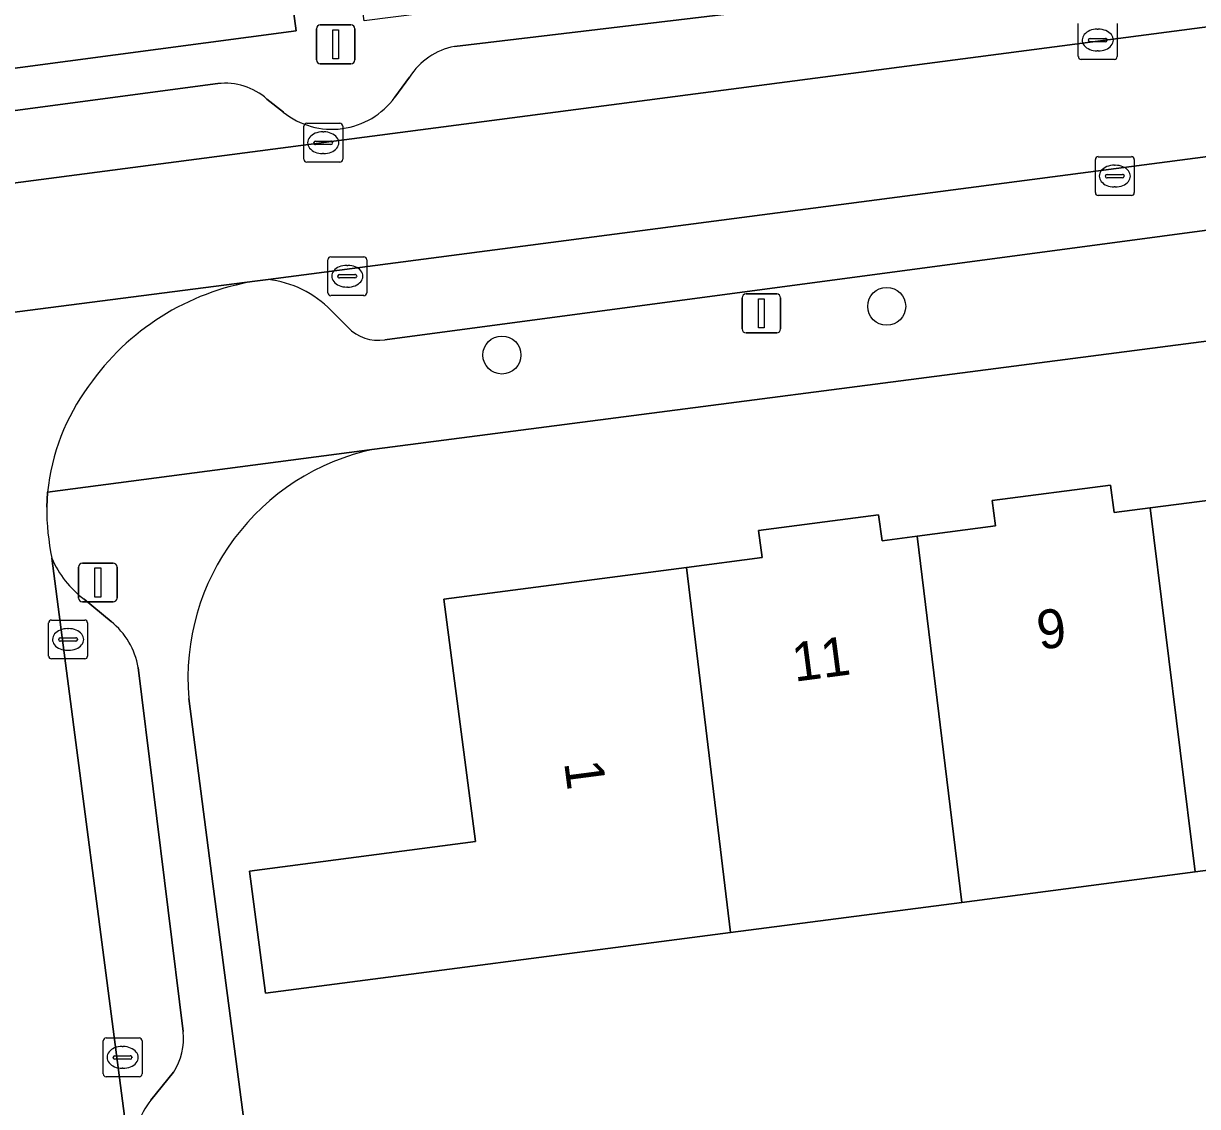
# Model space of a CAD drawing. Extents: x 162073 to 163043, y 381818 to 382561.
# Drawn here: x 162410.5 to 162440.71, y 382437.39 to 382465.27 of the extents above; entities that cross this region are included whole.
import ezdxf

# ---------------------------------------------------------------- set-up
doc = ezdxf.new("R2010")
doc.units = 0
for name, color, linetype in [('IMGEO_Boom', 7, 'Continuous'), ('IMGEO_Erf', 7, 'Continuous'), ('IMGEO_Groenvoorziening', 7, 'Continuous'), ('IMGEO_Kolk', 7, 'Continuous'), ('IMGEO_Lichtmast', 7, 'Continuous'), ('IMGEO_Muur', 7, 'Continuous'), ('IMGEO_Pand', 7, 'Continuous'), ('IMGEO_Pand_nummerreeks', 7, 'Continuous'), ('IMGEO_Parkeervlak_open', 7, 'Continuous'), ('IMGEO_Rijbaan_lokaal_open', 7, 'Continuous'), ('IMGEO_Voetpad_open', 7, 'Continuous')]:
    doc.layers.add(name, color=color, linetype=linetype)

msp = doc.modelspace()

# ---------------------------------------------------------------- linework, layer by layer
at = {"layer": 'IMGEO_Boom'}
for centre in [(162432.708, 382457.989), (162422.807, 382456.736)]:
    msp.add_circle(centre, 0.489, dxfattribs=at)
at = {"layer": 'IMGEO_Erf'}
for points in [[(162462.605, 382459.91), (162419.532, 382454.313)], [(162446.564, 382444.204), (162440.645, 382443.431), (162434.645, 382442.648), (162428.685, 382441.87), (162416.724, 382440.308), (162416.313, 382443.452), (162422.131, 382444.212), (162421.316, 382450.456), (162427.553, 382451.271), (162429.5, 382451.525), (162429.41, 382452.218), (162432.501, 382452.622), (162432.588, 382451.956), (162433.495, 382452.075), (162435.509, 382452.338), (162435.424, 382452.989), (162438.469, 382453.386), (162438.561, 382452.68), (162439.485, 382452.801), (162441.425, 382453.054)], [(162414.747, 382447.893), (162415.345, 382443.326), (162417.254, 382428.746)]]:
    msp.add_lwpolyline(points, dxfattribs=at)
msp.add_arc((162420.754, 382448.409), 6.029, 101.6965, 184.9072, dxfattribs=at)
at = {"layer": 'IMGEO_Groenvoorziening'}
msp.add_lwpolyline([(162416.769, 382470.6), (162396.812, 382467.987), (162397.548, 382462.43), (162417.516, 382465.082)], close=True, dxfattribs=at)
at = {"layer": 'IMGEO_Kolk'}
for p, q in [((162437.639, 382464.417), (162437.639, 382465.269)), ((162438.127, 382465.123), (162438.152, 382465.123)), ((162438.64, 382465.269), (162438.64, 382464.417)), ((162437.898, 382464.837), (162437.898, 382464.849)), ((162438.336, 382464.8), (162437.938, 382464.8)), ((162437.941, 382464.886), (162438.339, 382464.886)), ((162438.382, 382464.849), (162438.382, 382464.837)), ((162438.15, 382464.563), (162438.125, 382464.563)), ((162438.566, 382464.343), (162437.714, 382464.343)), ((162417.783, 382462.699), (162418.635, 382462.699)), ((162417.708, 382461.773), (162417.708, 382462.625)), ((162418.196, 382462.479), (162418.221, 382462.479)), ((162418.709, 382462.625), (162418.709, 382461.773)), ((162417.967, 382462.193), (162417.967, 382462.205)), ((162418.405, 382462.156), (162418.007, 382462.156)), ((162418.01, 382462.242), (162418.408, 382462.242)), ((162418.451, 382462.205), (162418.451, 382462.193)), ((162418.219, 382461.919), (162418.194, 382461.919)), ((162438.078, 382460.915), (162438.078, 382461.767)), ((162438.153, 382461.841), (162439.005, 382461.841)), ((162439.079, 382461.767), (162439.079, 382460.915)), ((162418.635, 382461.699), (162417.783, 382461.699)), ((162438.566, 382461.621), (162438.591, 382461.621)), ((162438.337, 382461.335), (162438.337, 382461.347)), ((162438.775, 382461.298), (162438.377, 382461.298)), ((162438.38, 382461.384), (162438.778, 382461.384)), ((162438.821, 382461.347), (162438.821, 382461.335)), ((162439.005, 382460.841), (162438.153, 382460.841)), ((162438.589, 382461.061), (162438.564, 382461.061)), ((162418.326, 382458.338), (162418.326, 382459.19)), ((162418.401, 382459.264), (162419.253, 382459.264)), ((162418.814, 382459.044), (162418.839, 382459.044)), ((162419.327, 382459.19), (162419.327, 382458.338)), ((162418.585, 382458.758), (162418.585, 382458.77)), ((162418.628, 382458.807), (162419.026, 382458.807)), ((162419.069, 382458.77), (162419.069, 382458.758)), ((162419.023, 382458.721), (162418.625, 382458.721)), ((162418.837, 382458.484), (162418.812, 382458.484)), ((162419.253, 382458.264), (162418.401, 382458.264)), ((162411.143, 382448.989), (162411.143, 382449.841)), ((162411.218, 382449.915), (162412.07, 382449.915)), ((162411.631, 382449.695), (162411.656, 382449.695)), ((162412.144, 382449.841), (162412.144, 382448.989)), ((162411.402, 382449.409), (162411.402, 382449.421)), ((162411.84, 382449.372), (162411.442, 382449.372)), ((162411.445, 382449.458), (162411.843, 382449.458)), ((162411.886, 382449.421), (162411.886, 382449.409)), ((162411.654, 382449.135), (162411.629, 382449.135)), ((162412.07, 382448.915), (162411.218, 382448.915)), ((162412.62, 382439.159), (162413.472, 382439.159)), ((162412.545, 382438.233), (162412.545, 382439.085)), ((162413.033, 382438.939), (162413.058, 382438.939)), ((162413.546, 382439.085), (162413.546, 382438.233)), ((162412.804, 382438.653), (162412.804, 382438.665)), ((162413.242, 382438.616), (162412.844, 382438.616)), ((162412.847, 382438.702), (162413.245, 382438.702)), ((162413.288, 382438.665), (162413.288, 382438.653)), ((162413.056, 382438.379), (162413.031, 382438.379)), ((162413.472, 382438.159), (162412.62, 382438.159))]:
    msp.add_line(p, q, dxfattribs=at)
for points in [[(162437.639, 382464.417), (162437.639, 382465.269)], [(162438.64, 382465.269), (162438.64, 382464.417)], [(162438.566, 382464.343), (162437.714, 382464.343)], [(162417.783, 382462.699), (162418.635, 382462.699)], [(162417.708, 382461.773), (162417.708, 382462.625)], [(162418.709, 382462.625), (162418.709, 382461.773)], [(162438.078, 382460.915), (162438.078, 382461.767)], [(162438.153, 382461.841), (162439.005, 382461.841)], [(162439.079, 382461.767), (162439.079, 382460.915)], [(162418.635, 382461.699), (162417.783, 382461.699)], [(162439.005, 382460.841), (162438.153, 382460.841)], [(162418.326, 382458.338), (162418.326, 382459.19)], [(162418.401, 382459.264), (162419.253, 382459.264)], [(162419.327, 382459.19), (162419.327, 382458.338)], [(162419.253, 382458.264), (162418.401, 382458.264)], [(162411.143, 382448.989), (162411.143, 382449.841)], [(162411.218, 382449.915), (162412.07, 382449.915)], [(162412.144, 382449.841), (162412.144, 382448.989)], [(162412.07, 382448.915), (162411.218, 382448.915)], [(162412.62, 382439.159), (162413.472, 382439.159)], [(162412.545, 382438.233), (162412.545, 382439.085)], [(162413.546, 382439.085), (162413.546, 382438.233)], [(162413.472, 382438.159), (162412.62, 382438.159)]]:
    msp.add_lwpolyline(points, dxfattribs=at)
for centre, radius, start, end in [((162437.938, 382464.846), 0.0403, 85.8775, 175.7526), ((162437.935, 382464.836), 0.0366, 178.938, 274.7102), ((162438.339, 382464.843), 0.043, 264.8664, 352.4533), ((162438.343, 382464.848), 0.0386, 1.7309, 96.639), ((162437.716, 382464.419), 0.0765, 181.552, 268.448), ((162437.716, 382464.419), 0.0765, 181.552, 268.448), ((162438.564, 382464.419), 0.0765, 271.552, 358.448), ((162438.564, 382464.419), 0.0765, 271.552, 358.448), ((162417.785, 382462.623), 0.0765, 91.552, 178.448), ((162417.785, 382462.623), 0.0765, 91.552, 178.448), ((162418.633, 382462.623), 0.0765, 1.552, 88.448), ((162418.633, 382462.623), 0.0765, 1.552, 88.448), ((162418.007, 382462.202), 0.0403, 85.8775, 175.7526), ((162418.004, 382462.192), 0.0366, 178.938, 274.7102), ((162418.408, 382462.199), 0.043, 264.8664, 352.4533), ((162418.412, 382462.204), 0.0386, 1.7309, 96.639), ((162417.785, 382461.775), 0.0765, 181.552, 268.448), ((162417.785, 382461.775), 0.0765, 181.552, 268.448), ((162418.633, 382461.775), 0.0765, 271.552, 358.448), ((162418.633, 382461.775), 0.0765, 271.552, 358.448), ((162438.155, 382461.765), 0.0765, 91.552, 178.448), ((162438.155, 382461.765), 0.0765, 91.552, 178.448), ((162439.003, 382461.765), 0.0765, 1.552, 88.448), ((162439.003, 382461.765), 0.0765, 1.552, 88.448), ((162438.377, 382461.344), 0.0403, 85.8775, 175.7526), ((162438.374, 382461.334), 0.0366, 178.938, 274.7102), ((162438.778, 382461.341), 0.043, 264.8664, 352.4533), ((162438.782, 382461.346), 0.0386, 1.7309, 96.639), ((162438.155, 382460.917), 0.0765, 181.552, 268.448), ((162438.155, 382460.917), 0.0765, 181.552, 268.448), ((162439.003, 382460.917), 0.0765, 271.552, 358.448), ((162439.003, 382460.917), 0.0765, 271.552, 358.448), ((162418.403, 382459.188), 0.0765, 91.552, 178.448), ((162418.403, 382459.188), 0.0765, 91.552, 178.448), ((162419.251, 382459.188), 0.0765, 1.552, 88.448), ((162419.251, 382459.188), 0.0765, 1.552, 88.448), ((162418.625, 382458.767), 0.0403, 85.8775, 175.7526), ((162418.622, 382458.757), 0.0366, 178.938, 274.7102), ((162419.026, 382458.764), 0.043, 264.8664, 352.4533), ((162419.03, 382458.769), 0.0386, 1.7309, 96.639), ((162418.403, 382458.34), 0.0765, 181.552, 268.448), ((162418.403, 382458.34), 0.0765, 181.552, 268.448), ((162419.251, 382458.34), 0.0765, 271.552, 358.448), ((162419.251, 382458.34), 0.0765, 271.552, 358.448), ((162411.22, 382449.839), 0.0765, 91.552, 178.448), ((162411.22, 382449.839), 0.0765, 91.552, 178.448), ((162412.068, 382449.839), 0.0765, 1.552, 88.448), ((162412.068, 382449.839), 0.0765, 1.552, 88.448), ((162411.442, 382449.418), 0.0403, 85.8775, 175.7526), ((162411.439, 382449.408), 0.0366, 178.938, 274.7102), ((162411.843, 382449.415), 0.043, 264.8664, 352.4533), ((162411.847, 382449.42), 0.0386, 1.7309, 96.639), ((162411.22, 382448.991), 0.0765, 181.552, 268.448), ((162411.22, 382448.991), 0.0765, 181.552, 268.448), ((162412.068, 382448.991), 0.0765, 271.552, 358.448), ((162412.068, 382448.991), 0.0765, 271.552, 358.448), ((162412.622, 382439.083), 0.0765, 91.552, 178.448), ((162412.622, 382439.083), 0.0765, 91.552, 178.448), ((162413.47, 382439.083), 0.0765, 1.552, 88.448), ((162413.47, 382439.083), 0.0765, 1.552, 88.448), ((162412.844, 382438.662), 0.0403, 85.8775, 175.7526), ((162412.841, 382438.652), 0.0366, 178.938, 274.7102), ((162413.245, 382438.659), 0.043, 264.8664, 352.4533), ((162413.249, 382438.664), 0.0386, 1.7309, 96.639), ((162412.622, 382438.235), 0.0765, 181.552, 268.448), ((162412.622, 382438.235), 0.0765, 181.552, 268.448), ((162413.47, 382438.235), 0.0765, 271.552, 358.448), ((162413.47, 382438.235), 0.0765, 271.552, 358.448)]:
    msp.add_arc(centre, radius, start, end, dxfattribs=at)
for centre, major_axis, ratio, start_param, end_param in [((162438.126, 382464.843), (-0.387, 0.002), 0.722429, 4.712389, 7.853982), ((162438.151, 382464.843), (-0.39, 0.002), 0.717154, 1.570796, 4.712389), ((162418.195, 382462.199), (-0.387, 0.002), 0.722429, 4.712389, 7.853982), ((162418.22, 382462.199), (-0.39, 0.002), 0.717154, 1.570796, 4.712389), ((162438.565, 382461.341), (-0.387, 0.002), 0.722429, 4.712389, 7.853982), ((162438.59, 382461.341), (-0.39, 0.002), 0.717154, 1.570796, 4.712389), ((162418.813, 382458.764), (-0.387, 0.002), 0.722429, 4.712389, 7.853982), ((162418.838, 382458.764), (-0.39, 0.002), 0.717154, 1.570796, 4.712389), ((162411.63, 382449.415), (-0.387, 0.002), 0.722429, 4.712389, 7.853982), ((162411.655, 382449.415), (-0.39, 0.002), 0.717154, 1.570796, 4.712389), ((162413.032, 382438.659), (-0.387, 0.002), 0.722429, 4.712389, 7.853982), ((162413.057, 382438.659), (-0.39, 0.002), 0.717154, 1.570796, 4.712389)]:
    msp.add_ellipse(centre, major_axis=major_axis, ratio=ratio, start_param=start_param, end_param=end_param, dxfattribs=at)
at = {"layer": 'IMGEO_Lichtmast'}
for p, q in [((162418.033, 382464.332), (162418.033, 382465.132)), ((162418.033, 382465.132), (162418.033, 382464.332)), ((162418.133, 382465.232), (162418.923, 382465.232)), ((162418.923, 382465.232), (162418.133, 382465.232)), ((162419.023, 382465.132), (162419.023, 382464.332)), ((162419.023, 382464.332), (162419.023, 382465.132)), ((162418.923, 382464.232), (162418.133, 382464.232)), ((162418.133, 382464.232), (162418.923, 382464.232)), ((162428.988, 382457.407), (162428.988, 382458.207)), ((162428.988, 382458.207), (162428.988, 382457.407)), ((162429.088, 382458.307), (162429.878, 382458.307)), ((162429.878, 382458.307), (162429.088, 382458.307)), ((162429.978, 382458.207), (162429.978, 382457.407)), ((162429.978, 382457.407), (162429.978, 382458.207)), ((162429.878, 382457.307), (162429.088, 382457.307)), ((162429.088, 382457.307), (162429.878, 382457.307)), ((162411.912, 382450.48), (162411.912, 382451.28)), ((162411.912, 382451.28), (162411.912, 382450.48)), ((162412.012, 382451.38), (162412.802, 382451.38)), ((162412.802, 382451.38), (162412.012, 382451.38)), ((162412.902, 382451.28), (162412.902, 382450.48)), ((162412.902, 382450.48), (162412.902, 382451.28)), ((162412.802, 382450.38), (162412.012, 382450.38)), ((162412.012, 382450.38), (162412.802, 382450.38))]:
    msp.add_line(p, q, dxfattribs=at)
for points in [[(162418.453, 382465.107), (162418.603, 382465.107), (162418.603, 382464.357), (162418.453, 382464.357), (162418.453, 382465.107)], [(162429.408, 382458.182), (162429.558, 382458.182), (162429.558, 382457.432), (162429.408, 382457.432), (162429.408, 382458.182)], [(162412.332, 382451.255), (162412.482, 382451.255), (162412.482, 382450.505), (162412.332, 382450.505), (162412.332, 382451.255)]]:
    msp.add_lwpolyline(points, dxfattribs=at)
for centre, start, end in [((162418.133, 382465.132), 90, 180), ((162418.133, 382465.132), 90, 180), ((162418.923, 382465.132), 0, 90), ((162418.923, 382465.132), 360, 90), ((162418.133, 382464.332), 180, 270), ((162418.133, 382464.332), 180, 270), ((162418.923, 382464.332), 270, 0), ((162418.923, 382464.332), 270, 0), ((162429.088, 382458.207), 90, 180), ((162429.088, 382458.207), 90, 180), ((162429.878, 382458.207), 0, 90), ((162429.878, 382458.207), 360, 90), ((162429.088, 382457.407), 180, 270), ((162429.088, 382457.407), 180, 270), ((162429.878, 382457.407), 270, 0), ((162429.878, 382457.407), 270, 0), ((162412.012, 382451.28), 90, 180), ((162412.012, 382451.28), 90, 180), ((162412.802, 382451.28), 0, 90), ((162412.802, 382451.28), 360, 90), ((162412.012, 382450.48), 180, 270), ((162412.012, 382450.48), 180, 270), ((162412.802, 382450.48), 270, 0), ((162412.802, 382450.48), 270, 0)]:
    msp.add_arc(centre, 0.1, start, end, dxfattribs=at)
at = {"layer": 'IMGEO_Muur'}
msp.add_lwpolyline([(162415.345, 382443.326), (162417.254, 382428.746)], dxfattribs=at)
at = {"layer": 'IMGEO_Pand'}
for points in [[(162439.485, 382452.801), (162440.645, 382443.431), (162446.564, 382444.204), (162445.442, 382453.596), (162444.528, 382453.477), (162444.448, 382454.092), (162441.342, 382453.686), (162441.425, 382453.054)], [(162439.485, 382452.801), (162438.561, 382452.68), (162438.469, 382453.386), (162435.424, 382452.989), (162435.509, 382452.338), (162433.495, 382452.075), (162434.645, 382442.648), (162440.645, 382443.431)], [(162428.685, 382441.87), (162434.645, 382442.648), (162433.495, 382452.075), (162432.588, 382451.956), (162432.501, 382452.622), (162429.41, 382452.218), (162429.5, 382451.525), (162427.553, 382451.271)], [(162428.685, 382441.87), (162427.553, 382451.271), (162421.316, 382450.456), (162422.131, 382444.212), (162416.313, 382443.452), (162416.724, 382440.308)]]:
    msp.add_lwpolyline(points, close=True, dxfattribs=at)
at = {"layer": 'IMGEO_Parkeervlak_open'}
for points in [[(162354.468, 382453.854), (162463.823, 382468.189)], [(162437.175, 382466.537), (162421.584, 382464.68)], [(162464.101, 382464.878), (162416.788, 382458.681)], [(162420.431, 382463.891), (162420.05, 382463.37)], [(162415.5, 382463.72), (162400.107, 382461.672)], [(162417.182, 382462.989), (162416.761, 382463.322)], [(162419.794, 382457.129), (162459.803, 382462.461)], [(162418.41, 382457.885), (162418.844, 382457.454)], [(162411.224, 382451.509), (162413.205, 382436.288), (162413.211, 382436.241)], [(162412.751, 382449.874), (162412.057, 382450.451)], [(162414.608, 382439.321), (162413.446, 382448.695)], [(162413.769, 382437.561), (162414.357, 382438.274)]]:
    msp.add_lwpolyline(points, dxfattribs=at)
for centre, radius, start, end in [((162421.925, 382462.945), 1.768, 101.1166, 147.6512), ((162415.686, 382462.113), 1.618, 48.3582, 96.608), ((162418.435, 382464.542), 1.996, 231.1066, 324.0277), ((162416.476, 382455.994), 2.705, 44.3506, 83.3702), ((162419.611, 382458.144), 1.031, 221.9828, 280.245), ((162413.606, 382452.527), 2.591, 203.1506, 233.2786), ((162411.557, 382448.376), 1.916, 9.5942, 51.443), ((162412.969, 382439.16), 1.647, 327.4419, 5.5956), ((162416.51, 382435.624), 3.356, 144.7572, 169.4126)]:
    msp.add_arc(centre, radius, start, end, dxfattribs=at)
at = {"layer": 'IMGEO_Rijbaan_lokaal_open'}
msp.add_lwpolyline([(162464.101, 382464.878), (162463.823, 382468.189), (162354.468, 382453.854), (162351.85, 382453.585), (162352.256, 382450.197), (162352.352, 382450.204), (162352.448, 382450.209), (162401.436, 382456.696), (162401.618, 382456.72), (162416.452, 382458.635), (162416.788, 382458.681)], close=True, dxfattribs=at)
for points in [[(162416.452, 382458.635), (162401.618, 382456.72)], [(162411.092, 382452.82), (162411.117, 382453.202)], [(162414.35, 382427.411), (162414.317, 382427.668), (162413.837, 382431.43), (162413.211, 382436.241), (162413.205, 382436.288), (162411.224, 382451.509)]]:
    msp.add_lwpolyline(points, dxfattribs=at)
for centre, radius, start, end in [((162417.496, 382452.236), 6.484, 99.2628, 145.1897), ((162416.615, 382452.652), 5.526, 143.524, 174.2887), ((162417.614, 382452.815), 6.522, 179.9524, 191.5467)]:
    msp.add_arc(centre, radius, start, end, dxfattribs=at)
at = {"layer": 'IMGEO_Voetpad_open'}
for points in [[(162462.024, 382470.821), (162441.489, 382468.16), (162440.79, 382473.744), (162438.951, 382473.504), (162439.679, 382467.926), (162419.261, 382465.333), (162418.51, 382470.827), (162416.769, 382470.6), (162417.516, 382465.082), (162397.548, 382462.43), (162396.812, 382467.987), (162395.012, 382467.752), (162395.761, 382462.198), (162373.908, 382459.306), (162373.173, 382464.892), (162371.398, 382464.66), (162372.148, 382459.072), (162351.881, 382456.381), (162351.85, 382453.585), (162354.468, 382453.854)], [(162421.584, 382464.68), (162437.175, 382466.537)], [(162420.05, 382463.37), (162420.431, 382463.891)], [(162400.107, 382461.672), (162415.5, 382463.72)], [(162416.761, 382463.322), (162417.182, 382462.989)], [(162461.243, 382462.662), (162459.803, 382462.461), (162419.794, 382457.129)], [(162411.117, 382453.202), (162419.532, 382454.313), (162462.605, 382459.91)], [(162416.788, 382458.681), (162416.452, 382458.635)], [(162418.844, 382457.454), (162418.41, 382457.885)], [(162419.532, 382454.313), (162411.117, 382453.202), (162411.092, 382452.82)], [(162412.057, 382450.451), (162412.751, 382449.874)], [(162413.446, 382448.695), (162414.608, 382439.321)], [(162415.345, 382443.326), (162414.747, 382447.893)], [(162432.658, 382288.337), (162432.711, 382287.912), (162433.14, 382283.892), (162433.079, 382281.915), (162436.323, 382283.097), (162432.965, 382308.744), (162432.779, 382310.167), (162427.267, 382352.264), (162427.08, 382353.697), (162422.348, 382389.839), (162422.167, 382391.222), (162417.448, 382427.262), (162417.254, 382428.746), (162415.345, 382443.326)], [(162414.357, 382438.274), (162413.769, 382437.561)]]:
    msp.add_lwpolyline(points, dxfattribs=at)
for centre, radius, start, end in [((162421.925, 382462.945), 1.768, 101.1166, 147.6512), ((162415.686, 382462.113), 1.618, 48.3582, 96.608), ((162418.435, 382464.542), 1.996, 231.1066, 324.0277), ((162417.496, 382452.236), 6.484, 99.2628, 145.1897), ((162416.476, 382455.994), 2.705, 44.3506, 83.3702), ((162419.611, 382458.144), 1.031, 221.9828, 280.245), ((162416.615, 382452.652), 5.526, 143.524, 174.2887), ((162420.754, 382448.409), 6.029, 101.6965, 184.9072), ((162417.614, 382452.815), 6.522, 179.9524, 191.5467), ((162413.606, 382452.527), 2.591, 203.1506, 233.2786), ((162411.557, 382448.376), 1.916, 9.5942, 51.443), ((162412.969, 382439.16), 1.647, 327.4419, 5.5956), ((162416.51, 382435.624), 3.356, 144.7572, 169.4126)]:
    msp.add_arc(centre, radius, start, end, dxfattribs=at)

# ---------------------------------------------------------------- texts
at = {"layer": 'IMGEO_Pand_nummerreeks'}
for s, rotation, p in [('9', 7.4443, (162436.64, 382449.149)), ('11', 7.4443, (162430.34, 382448.326)), ('1', 277.4365, (162424.406, 382446.247))]:
    msp.add_text(s, height=1, rotation=rotation, dxfattribs=at).set_placement(p)

doc.saveas('drawing.dxf')
